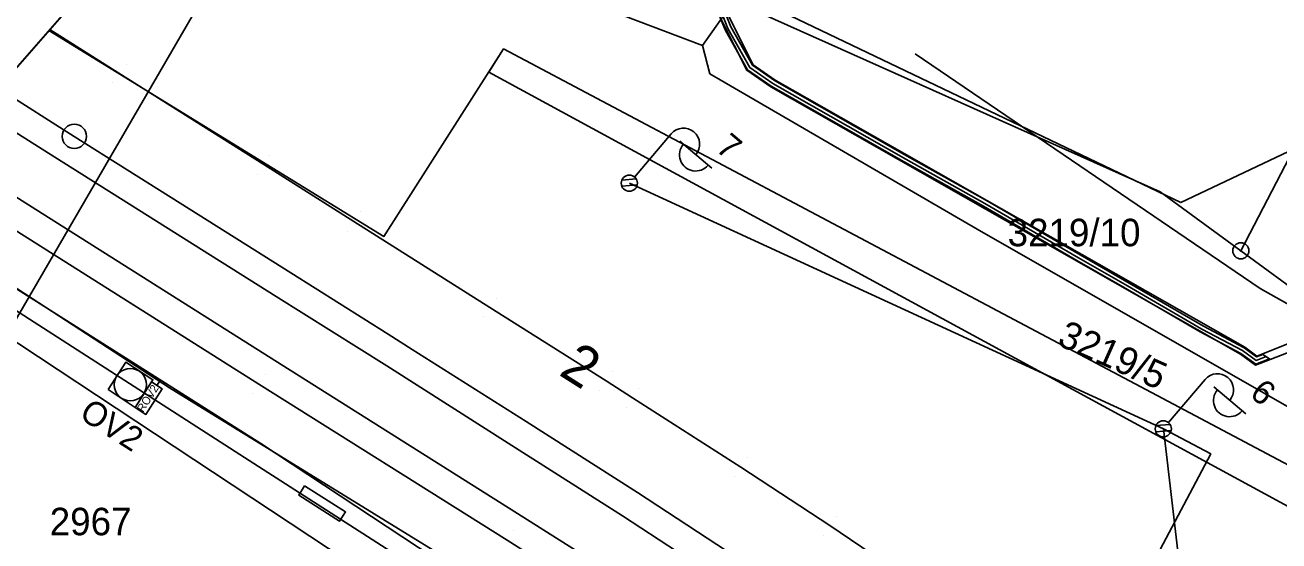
# Model space of a CAD drawing. Extents: x -620475 to -619963, y -1123010 to -1122510.
# Drawn here: x -620377.4 to -620299.9, y -1122652.4 to -1122620.5 of the extents above; entities that cross this region are included whole.
import ezdxf

# ---------------------------------------------------------------- set-up
doc = ezdxf.new("R2010")
doc.units = 0
for name, color, linetype in [('060601_EOV', 7, 'Continuous'), ('060604_ROZVODY_SEE', 7, 'Continuous'), ('CETIN', 7, 'Continuous'), ('EON-podzemní NN', 7, 'Continuous'), ('HranDP', 7, 'Continuous'), ('Hranice parcel', 7, 'Continuous'), ('Parcelní čísla', 7, 'Continuous'), ('PS 06-14-01_trasa_sdělovací_nové', 7, 'Continuous'), ('Rámečky', 7, 'Continuous'), ('Rámečky-tisk', 7, 'Continuous'), ('SEE', 7, 'Continuous'), ('SSZT', 7, 'Continuous'), ('STÁVAJÍCÍ STOŽÁRY ODHAD', 7, 'Continuous'), ('UZEMNĚNÍ', 7, 'Continuous'), ('VAS vodovod', 7, 'Continuous'), ('Vrstva 1', 7, 'Continuous'), ('Vrstva 12', 7, 'Continuous'), ('Vrstva 14', 7, 'Continuous'), ('Vrstva 23', 7, 'Continuous'), ('Vrstva 25', 7, 'Continuous'), ('Vrstva 62', 7, 'Continuous'), ('Vrstva 7', 7, 'Continuous'), ('Věcná břemena k části', 7, 'Continuous'), ('Značky bodu BP', 7, 'Continuous')]:
    doc.layers.add(name, color=color, linetype=linetype)

msp = doc.modelspace()

# ---------------------------------------------------------------- linework, layer by layer
at = {"layer": '060601_EOV'}
msp.add_lwpolyline([(-620235.16, -1122712.242), (-620240.174, -1122718.342), (-620243.025, -1122715.998), (-620248.321, -1122722.765), (-620259.889, -1122713.575), (-620277.713, -1122700.902), (-620282.346, -1122705.302), (-620297.82, -1122689.49), (-620304.222, -1122684.862), (-620310.815, -1122680.061), (-620322.228, -1122672.322), (-620343.182, -1122658.459), (-620368.499, -1122642.897), (-620385.559, -1122631.811)], dxfattribs=at)
at = {"layer": '060604_ROZVODY_SEE'}
msp.add_line((-620369.273, -1122642.748), (-620369.112, -1122642.5), dxfattribs=at)
for points in [[(-620316.822, -1122675.988), (-620307.569, -1122662.984), (-620311.113, -1122660.198), (-620304.112, -1122646.984), (-620307.038, -1122645.433), (-620340.053, -1122630.257)], [(-620243.025, -1122715.998), (-620248.321, -1122722.765), (-620259.889, -1122713.575), (-620277.713, -1122700.902), (-620282.346, -1122705.302), (-620297.82, -1122689.49), (-620304.222, -1122684.862), (-620310.815, -1122680.061), (-620316.822, -1122675.988), (-620322.228, -1122672.322), (-620326.634, -1122669.408), (-620343.182, -1122658.459), (-620368.499, -1122642.897), (-620385.559, -1122631.811)]]:
    msp.add_lwpolyline(points, dxfattribs=at)
msp.add_lwpolyline([(-620370.615, -1122644.115), (-620369.604, -1122642.536), (-620368.942, -1122642.96), (-620369.953, -1122644.539)], close=True, dxfattribs=at)
at = {"layer": 'CETIN'}
msp.add_lwpolyline([(-620322.39, -1122622.262), (-620301.06, -1122636.75), (-620273.539, -1122652.218), (-620253.246, -1122663.163), (-620204.022, -1122698.845), (-620159.643, -1122769.192), (-620144.669, -1122791.286), (-620140.333, -1122798.335), (-620134.98, -1122805.248), (-620121.226, -1122817.175), (-620095.953, -1122832.424), (-620068.004, -1122848.181)], dxfattribs=at)
at = {"layer": 'EON-podzemní NN'}
for points in [[(-620334.114, -1122619.778), (-620333.78, -1122620.599), (-620332.448, -1122622.968), (-620331.073, -1122623.916), (-620322.872, -1122628.592), (-620317.971, -1122631.332), (-620312.19, -1122634.683), (-620309.15, -1122636.423), (-620304.563, -1122639.091), (-620302.034, -1122640.426), (-620301.271, -1122640.98), (-620300.896, -1122640.835), (-620300.476, -1122641.101), (-620301.329, -1122641.432), (-620302.246, -1122640.766), (-620304.757, -1122639.441), (-620309.35, -1122636.769), (-620312.39, -1122635.029), (-620318.169, -1122631.68), (-620323.068, -1122628.94), (-620331.287, -1122624.255), (-620332.752, -1122623.244), (-620334.14, -1122620.773), (-620334.632, -1122619.567)], [(-620300.686, -1122640.968), (-620301.3, -1122641.206), (-620302.14, -1122640.596), (-620304.66, -1122639.266), (-620309.25, -1122636.596), (-620312.29, -1122634.856), (-620318.07, -1122631.506), (-620322.97, -1122628.766), (-620331.18, -1122624.086), (-620332.6, -1122623.106), (-620333.96, -1122620.686), (-620334.384, -1122619.644)]]:
    msp.add_lwpolyline(points, dxfattribs=at)
at = {"layer": 'HranDP'}
msp.add_line((-620358.11, -1122613.18), (-620335.54, -1122621.75), dxfattribs=at)
for points in [[(-620297.09, -1122645.35), (-620318.55, -1122633.1), (-620335.09, -1122623.49), (-620335.54, -1122621.75)], [(-620310.57, -1122708.76), (-620306.2, -1122698.65), (-620309.9, -1122688.62), (-620334.71, -1122668.63), (-620387.366, -1122633.877)]]:
    msp.add_lwpolyline(points, dxfattribs=at)
at = {"layer": 'Hranice parcel'}
for p, q in [((-620358.11, -1122613.18), (-620335.54, -1122621.75)), ((-620335.54, -1122621.75), (-620333.59, -1122619.01)), ((-620302.25, -1122634.43), (-620294.15, -1122618.83))]:
    msp.add_line(p, q, dxfattribs=at)
for points in [[(-620333.59, -1122619.01), (-620307.23, -1122630.79), (-620302.25, -1122634.43)], [(-620296.23, -1122649.3), (-620347.83, -1122621.96), (-620355.23, -1122633.54), (-620375.943, -1122620.818)], [(-620297.09, -1122645.35), (-620318.55, -1122633.1), (-620335.09, -1122623.49), (-620335.54, -1122621.75)], [(-620310.57, -1122708.76), (-620306.2, -1122698.65), (-620309.9, -1122688.62), (-620334.71, -1122668.63), (-620387.366, -1122633.877)], [(-620302.25, -1122634.43), (-620301.71, -1122634.83), (-620292.25, -1122641.75)]]:
    msp.add_lwpolyline(points, dxfattribs=at)
at = {"layer": 'PS 06-14-01_trasa_sdělovací_nové'}
msp.add_lwpolyline([(-620248.321, -1122722.765), (-620259.889, -1122713.575), (-620277.711, -1122700.887), (-620282.346, -1122705.302), (-620297.82, -1122689.49), (-620310.815, -1122680.061), (-620322.228, -1122672.322), (-620343.182, -1122658.459), (-620368.499, -1122642.897), (-620385.559, -1122631.811)], dxfattribs=at)
at = {"layer": 'Rámečky'}
msp.add_lwpolyline([(-620279.069, -1122510.073), (-620474.613, -1122733.616), (-620158.492, -1123010.143)], dxfattribs=at)
at = {"layer": 'Rámečky-tisk'}
msp.add_line((-620351.118, -1122592.438), (-620471.937, -1122730.556), dxfattribs=at)
for points in [[(-620279.069, -1122510.073), (-620474.613, -1122733.616), (-620158.492, -1123010.143)], [(-620471.937, -1122730.556), (-620441.664, -1122748.159), (-620351.118, -1122592.438)]]:
    msp.add_lwpolyline(points, dxfattribs=at)
at = {"layer": 'SEE'}
for points in [[(-620340.053, -1122630.257), (-620307.038, -1122645.433), (-620304.995, -1122662.882), (-620304.721, -1122665.223), (-620302.66, -1122666.96), (-620305.446, -1122670.265), (-620283.044, -1122687.742), (-620274.947, -1122694.711), (-620269.357, -1122688.084), (-620267.489, -1122689.555)], [(-620244.518, -1122694.296), (-620246.547, -1122692.66), (-620267.469, -1122718.6), (-620268.222, -1122719.534), (-620284.407, -1122704.62), (-620304.333, -1122686.26), (-620309.55, -1122681.453), (-620327.714, -1122669.483), (-620362.834, -1122646.339), (-620385.658, -1122631.923)]]:
    msp.add_lwpolyline(points, dxfattribs=at)
at = {"layer": 'SSZT'}
msp.add_lwpolyline([(-620386.367, -1122632.734), (-620363.271, -1122647.563), (-620313.966, -1122679.218), (-620306.51, -1122669.289), (-620273.137, -1122696.274), (-620258.422, -1122709.142), (-620248.072, -1122696.094)], dxfattribs=at)
at = {"layer": 'STÁVAJÍCÍ STOŽÁRY ODHAD'}
for p, q in [((-620339.738, -1122629.872), (-620337.476, -1122627.201)), ((-620336.942, -1122627.653), (-620334.958, -1122629.333)), ((-620340.52, -1122630.056), (-620339.643, -1122629.984)), ((-620340.526, -1122630.433), (-620339.572, -1122630.354)), ((-620306.723, -1122645.048), (-620304.461, -1122642.377)), ((-620303.927, -1122642.829), (-620301.943, -1122644.509)), ((-620307.511, -1122645.609), (-620306.557, -1122645.53)), ((-620307.505, -1122645.233), (-620306.628, -1122645.16))]:
    msp.add_line(p, q, dxfattribs=at)
for centre in [(-620340.061, -1122630.254), (-620307.046, -1122645.43)]:
    msp.add_circle(centre, 0.5, dxfattribs=at)
for centre, start, end in [((-620336.713, -1122627.847), 319.74828, 139.74828), ((-620335.958, -1122628.503), 139.04571, 320.45085), ((-620303.698, -1122643.023), 319.74828, 139.74828), ((-620302.943, -1122643.679), 139.04571, 320.45085)]:
    msp.add_arc(centre, 1, start, end, dxfattribs=at)
at = {"layer": 'UZEMNĚNÍ'}
msp.add_lwpolyline([(-620302.826, -1122665.182), (-620303.546, -1122666.133), (-620307.569, -1122662.984), (-620311.113, -1122660.198), (-620304.112, -1122646.984), (-620307.038, -1122645.433), (-620340.053, -1122630.257)], dxfattribs=at)
at = {"layer": 'VAS vodovod'}
msp.add_lwpolyline([(-620286.624, -1122632.599), (-620287.076, -1122632.394), (-620297.742, -1122627.557), (-620305.959, -1122631.453), (-620337.213, -1122616.495), (-620336.268, -1122613.965)], dxfattribs=at)
at = {"layer": 'Vrstva 1'}
for points in [[(-620375.899, -1122620.767), (-620371.626, -1122623.45), (-620362.665, -1122629.103), (-620357.095, -1122632.621), (-620348.688, -1122637.935), (-620341.5, -1122642.47), (-620339.854, -1122643.512), (-620333.156, -1122647.798), (-620327.653, -1122651.408), (-620321.139, -1122655.817), (-620314.146, -1122660.717), (-620307.245, -1122665.745), (-620300.366, -1122670.953), (-620293.063, -1122676.601)], [(-620379.075, -1122624.398), (-620379.008, -1122624.44), (-620374.378, -1122627.361), (-620367.833, -1122631.489), (-620360.993, -1122635.8), (-620354.976, -1122639.588), (-620353.476, -1122640.528), (-620346.441, -1122644.972), (-620339.555, -1122649.372), (-620332.789, -1122653.783), (-620326.854, -1122657.769), (-620323.491, -1122660.075), (-620319.328, -1122662.995), (-620318.623, -1122663.494), (-620316.382, -1122665.099), (-620314.967, -1122666.125), (-620314.061, -1122666.783), (-620307.461, -1122671.648), (-620300.906, -1122676.615), (-620294.546, -1122681.556)], [(-620379.075, -1122624.398), (-620379.008, -1122624.44), (-620374.378, -1122627.361), (-620367.833, -1122631.489), (-620360.993, -1122635.8), (-620354.976, -1122639.588), (-620353.476, -1122640.528), (-620346.441, -1122644.972), (-620339.555, -1122649.372), (-620332.789, -1122653.783), (-620326.854, -1122657.769), (-620323.491, -1122660.075), (-620319.328, -1122662.995), (-620318.623, -1122663.494), (-620316.382, -1122665.099), (-620314.967, -1122666.125), (-620314.061, -1122666.783), (-620307.461, -1122671.648), (-620300.906, -1122676.615), (-620294.546, -1122681.556)], [(-620383.649, -1122629.627), (-620378.269, -1122633.015), (-620362.958, -1122642.66), (-620347.616, -1122652.305), (-620342.456, -1122655.575), (-620322.526, -1122668.083), (-620312.925, -1122674.13), (-620301.163, -1122681.549), (-620292.126, -1122687.227), (-620282.992, -1122692.997), (-620276.394, -1122697.25), (-620266.758, -1122703.956), (-620255.894, -1122712.191)], [(-620326.634, -1122669.408), (-620343.182, -1122658.459), (-620368.499, -1122642.897), (-620385.559, -1122631.811)]]:
    msp.add_lwpolyline(points, dxfattribs=at)
at = {"layer": 'Vrstva 12'}
msp.add_lwpolyline([(-620372.277, -1122643.002), (-620371.199, -1122641.317), (-620369.514, -1122642.395), (-620370.615, -1122644.115), (-620372.277, -1122643.002)], dxfattribs=at)
at = {"layer": 'Vrstva 14'}
for points in [[(-620382.462, -1122628.27), (-620376.978, -1122631.728), (-620361.983, -1122641.198), (-620346.591, -1122650.915), (-620335.3, -1122658.037), (-620326.919, -1122663.23), (-620325.66, -1122664.016), (-620320.659, -1122667.355), (-620319.405, -1122668.214), (-620318.806, -1122667.396), (-620318.045, -1122667.942), (-620316.915, -1122666.32), (-620319.344, -1122664.58), (-620319.636, -1122664.917), (-620324.475, -1122661.491), (-620327.8, -1122659.174), (-620333.678, -1122655.247), (-620340.478, -1122650.803), (-620347.325, -1122646.469), (-620355.043, -1122641.547), (-620361.891, -1122637.249), (-620368.728, -1122632.945), (-620375.571, -1122628.636), (-620379.873, -1122625.938)], [(-620380.227, -1122625.715), (-620379.873, -1122625.938), (-620375.571, -1122628.636), (-620368.728, -1122632.945), (-620361.891, -1122637.249), (-620355.043, -1122641.547), (-620347.325, -1122646.469), (-620340.478, -1122650.803), (-620333.678, -1122655.247), (-620327.8, -1122659.174), (-620324.475, -1122661.491), (-620319.636, -1122664.917)]]:
    msp.add_lwpolyline(points, dxfattribs=at)
at = {"layer": 'Vrstva 23'}
msp.add_lwpolyline([(-620360.137, -1122648.953), (-620360.499, -1122649.524), (-620357.97, -1122651.129), (-620357.608, -1122650.559)], close=True, dxfattribs=at)
at = {"layer": 'Vrstva 25'}
msp.add_circle((-620370.91, -1122642.702), 1, dxfattribs=at)
at = {"layer": 'Vrstva 62'}
for p, q in [((-620371.167, -1122622.896), (-620371.167, -1122622.896)), ((-620372.005, -1122624.055), (-620372.005, -1122624.055)), ((-620362.289, -1122628.513), (-620362.289, -1122628.513)), ((-620363.041, -1122629.693), (-620363.041, -1122629.693)), ((-620356.707, -1122632.009), (-620356.707, -1122632.009)), ((-620357.484, -1122633.232), (-620357.484, -1122633.232)), ((-620348.295, -1122637.351), (-620348.295, -1122637.351)), ((-620349.081, -1122638.52), (-620349.081, -1122638.52)), ((-620362.573, -1122642.046), (-620362.573, -1122642.046)), ((-620341.101, -1122641.878), (-620341.101, -1122641.878)), ((-620363.343, -1122643.275), (-620363.343, -1122643.275)), ((-620341.899, -1122643.063), (-620341.899, -1122643.063)), ((-620339.473, -1122642.921), (-620339.473, -1122642.921)), ((-620340.236, -1122644.103), (-620340.236, -1122644.103)), ((-620332.764, -1122647.217), (-620332.764, -1122647.217)), ((-620333.548, -1122648.38), (-620333.548, -1122648.38)), ((-620327.268, -1122650.821), (-620327.268, -1122650.821)), ((-620347.227, -1122651.706), (-620347.227, -1122651.706)), ((-620328.038, -1122651.995), (-620328.038, -1122651.995))]:
    msp.add_line(p, q, dxfattribs=at)
at = {"layer": 'Vrstva 7'}
msp.add_circle((-620374.378, -1122627.361), 0.75, dxfattribs=at)
msp.add_circle((-620374.378, -1122627.361), 0.75, dxfattribs=at)
at = {"layer": 'Věcná břemena k části'}
for points in [[(-620298.73, -1122639.94), (-620301.26, -1122640.93), (-620302, -1122640.39), (-620331.05, -1122623.88), (-620332.41, -1122622.94), (-620334.05, -1122619.66)], [(-620334.39, -1122620.13), (-620332.8, -1122623.28), (-620331.31, -1122624.3), (-620302.28, -1122640.81), (-620301.34, -1122641.49), (-620298.51, -1122640.4)]]:
    msp.add_lwpolyline(points, dxfattribs=at)
msp.add_lwpolyline([(-620297.19, -1122651.39), (-620296.23, -1122649.3), (-620347.83, -1122621.96), (-620348.75, -1122623.39)], close=True, dxfattribs=at)
at = {"layer": 'Značky bodu BP'}
for radius in [0.5, 0.0303]:
    msp.add_circle((-620302.25, -1122634.43), radius, dxfattribs=at)

# ---------------------------------------------------------------- texts
at = {"layer": '060604_ROZVODY_SEE'}
msp.add_text('ROV2', height=0.5, rotation=57.37603, dxfattribs=at).set_placement((-620370.119, -1122644.445))
at = {"layer": 'Parcelní čísla'}
for s, p in [('3219/10', (-620316.67, -1122634.15)), ('2967', (-620375.897, -1122652.006))]:
    msp.add_text(s, height=1.7, dxfattribs=at).set_placement(p)
msp.add_text('3219/5', height=1.7, rotation=336, dxfattribs=at).set_placement((-620313.675, -1122640.221))
at = {"layer": 'STÁVAJÍCÍ STOŽÁRY ODHAD'}
for s, p in [('7', (-620334.782, -1122628.194)), ('6', (-620301.767, -1122643.37))]:
    msp.add_text(s, height=1.5, rotation=319.74828, dxfattribs=at).set_placement(p)
at = {"layer": 'Vrstva 1'}
msp.add_text('2', height=2.5, rotation=327.66415, dxfattribs=at).set_placement((-620344.488, -1122642.058))
at = {"layer": 'Vrstva 25'}
msp.add_text('OV2', height=1.5, rotation=327.35691, dxfattribs=at).set_placement((-620374.144, -1122644.732))

doc.saveas('drawing.dxf')
